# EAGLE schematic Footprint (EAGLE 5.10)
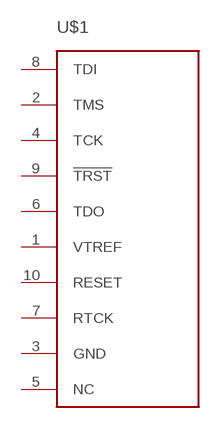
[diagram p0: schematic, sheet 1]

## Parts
U$1  TC2050-MCP-NL  [TC2030-MCP-NL]
Unconnected: U$1.1(VTREF) U$1.2(TMS) U$1.3(GND) U$1.4(TCK) U$1.5(NC) U$1.6(TDO) U$1.7(RTCK) U$1.8(TDI) U$1.9(!TRST) U$1.10(RESET)

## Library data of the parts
U$1 = TC2050:TC2050: TAG-CONNECT ISP Connector Manufacturer: Tag-Connect Cable for easy In-Circuit PCB Programming. Designed for JTAG 10 pin, suitable for many others. Pin Connection for TC2050 NL. PADDescription 1VTREF 2TMS 3GND 4TCK 5NC 6TDO 7RTCK 8TDI 9!TRST 10RESET ©2009 ROFA.cz Modified 7/2011 by Tim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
